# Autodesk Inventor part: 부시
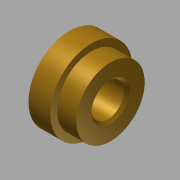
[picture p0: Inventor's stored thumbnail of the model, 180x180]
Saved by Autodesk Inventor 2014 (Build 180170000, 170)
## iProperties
Created: 2011-04
Part Number: 부시
Document SubType Name: Modeling
Designer: 한국산업디자인학원 [http://gmhk.co.kr]
Density: 7.86 g/cm^3
Material: 강철, 연강
Mass: 57.8082 g
Surface Area: 30.152 cm^2
Volume: 7.35473 cm^3
Appearance: 황동 - 새틴
Author: pww
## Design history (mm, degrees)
sketch "스케치1"
  geometry: L1 (0, 0)-(15, 0); L2 (0, 6)-(15, 6); L3 (15, 6)-(15, 12.5); L4 (15, 12.5)-(8, 12.5); L5 (8, 12.5)-(8, 15); L6 (8, 15)-(0, 15); L7 (0, 15)-(0, 6)
  constraints: 14 end point, 4 parallel, 2 vertical alignment, 1 horizontal, 1 perpendicular, 1 vertical
  dimensions: "d0" = 15 distance of L1.start L1.end; "d1" = 12 diameter of L2 L1; "d2" = 25 diameter of L4 L1; "d3" = 8 distance of L5.end L6.end; "d4" = 30 diameter of L6 L1
revolve "회전1" sketch "스케치1" stored, may be unused: angle "d5" = 90 deg
chamfer "모따기1" distance "d6" = 1; stored, may be unused: second distance "d7" = 2, angle "d8" = 45 deg
node "솔리드1"
